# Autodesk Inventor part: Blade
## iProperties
Shininess: 64.0
Length Units: 11272
Angle Units: 11279
Time Units: 11290
Mass Units: 11286
Length Display Precision: 4
Angle Display Precision: 2
Compacted: True
Part Number: Blade
Document SubType Name: Modeling
Created: 2003-08
Designer: jpittman
Manufacturer: Standard
Standards Organization: Custom
Density: 0.0
Volumn: 0.0
Area: 0.0
PropertySet Name: Model Information
Control State: 0
Master: False
Checked Out: False
Author: jpittman
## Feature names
1. Blade Body [Extrusion]
2. Fillet2
3. Extrusion3
4. Hole3
5. Hole4
6. Extrusion6
7. Hole8
8. Extrusion7
9. Fillet6
